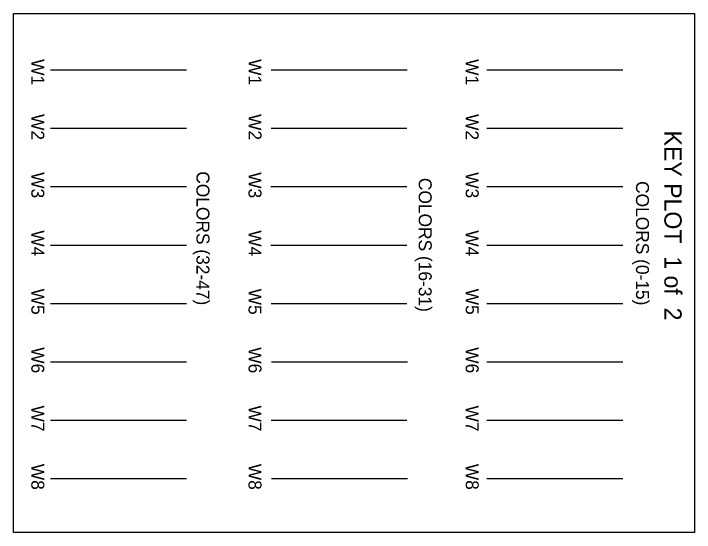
# Model space of a CAD drawing. Extents: x 2751 to 3858, y 6160 to 8366.
# Drawn here: x 2808 to 3858, y 7566 to 8366 of the extents above; entities that cross this region are included whole.
import ezdxf

# ---------------------------------------------------------------- set-up
doc = ezdxf.new("R2010")
doc.units = 0
doc.layers.add('Default', color=7, linetype='Continuous')

msp = doc.modelspace()

# ---------------------------------------------------------------- linework, layer by layer
at = {"layer": 'Default'}
for p, q in [((2865, 8278.8), (3074.6, 8278.8)), ((3205.4, 8278.8), (3414.9, 8278.8)), ((3537.9, 8278.8), (3747.5, 8278.8)), ((2865, 8188.8), (3074.6, 8188.8)), ((3205.1, 8188.8), (3414.7, 8188.8)), ((3537.9, 8188.8), (3747.5, 8188.8)), ((2865, 8098.8), (3074.6, 8098.8)), ((3205, 8098.8), (3414.6, 8098.8)), ((3537.9, 8098.8), (3747.5, 8098.8)), ((2865, 8008.8), (3074.6, 8008.8)), ((3205, 8008.8), (3414.6, 8008.8)), ((3537.9, 8008.8), (3747.5, 8008.8)), ((2865, 7918.8), (3074.6, 7918.8)), ((3205.2, 7918.8), (3414.8, 7918.8)), ((3537.9, 7918.8), (3747.5, 7918.8)), ((2865, 7828.8), (3074.6, 7828.8)), ((3205.9, 7828.8), (3415.5, 7828.8)), ((3537.9, 7828.8), (3747.5, 7828.8)), ((2865, 7738.8), (3074.6, 7738.8)), ((3205.2, 7738.8), (3414.8, 7738.8)), ((3537.9, 7738.8), (3747.5, 7738.8)), ((2865, 7648.8), (3074.6, 7648.8)), ((3205.9, 7648.8), (3415.5, 7648.8)), ((3537.9, 7648.8), (3747.5, 7648.8))]:
    msp.add_line(p, q, dxfattribs=at)
msp.add_lwpolyline([(2808.1, 8365.7), (3858.1, 8365.7), (3858.1, 7565.7), (2808.1, 7565.7)], close=True, dxfattribs=at)

# ---------------------------------------------------------------- texts
for s, height, p in [('W1', 20, (2835.4, 8295.5)), ('W1', 20, (2835.4, 8295.5)), ('W1', 20, (3170.4, 8295.5)), ('W1', 20, (3170.4, 8295.5)), ('W1', 20, (3505.4, 8295.5)), ('W2', 20, (2835.4, 8210.8)), ('W2', 20, (3170.4, 8210.8)), ('W2', 20, (3505.4, 8210.8)), ('KEY PLOT  1 of  2', 26.62, (3811.8, 8185.3)), ('W3', 20, (2835.4, 8121.1)), ('COLORS (32-47)', 20, (3090.1, 8122.5)), ('W3', 20, (3170.4, 8121.1)), ('W3', 20, (3505.4, 8121.1)), ('COLORS (16-31)', 20, (3432.9, 8112.3)), ('COLORS (0-15)', 20, (3768, 8107.4)), ('W4', 20, (2835.4, 8031.5)), ('W4', 20, (3170.4, 8031.5)), ('W4', 20, (3505.4, 8031.5)), ('W5', 20, (2835.4, 7941.5)), ('W5', 20, (3170.4, 7941.5)), ('W5', 20, (3505.4, 7941.5)), ('W6', 20, (2835.4, 7851.2)), ('W6', 20, (3170.4, 7851.2)), ('W6', 20, (3505.4, 7851.2)), ('W7', 20, (2835.4, 7761.3)), ('W7', 20, (3170.4, 7761.3)), ('W7', 20, (3505.4, 7761.3)), ('W8', 20, (2835.4, 7671.4)), ('W8', 20, (3170.4, 7671.4)), ('W8', 20, (3505.4, 7671.4))]:
    msp.add_text(s, height=height, rotation=270, dxfattribs=at).set_placement(p)

doc.saveas('drawing.dxf')
